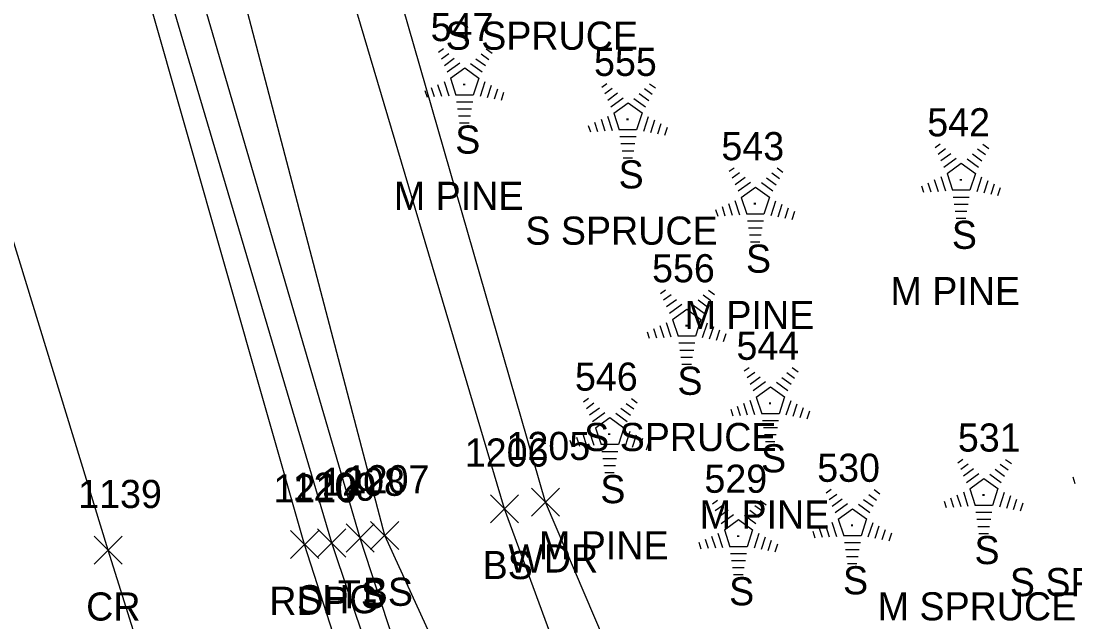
# Model space of a CAD drawing. Extents: x 1545627 to 1546562, y 571176 to 576667.
# Drawn here: x 1546172.5 to 1546247.4, y 571891 to 571933.8 of the extents above; entities that cross this region are included whole.
import ezdxf

# ---------------------------------------------------------------- set-up
doc = ezdxf.new("R2010")
doc.units = 0
for name, color, linetype in [('L_A', 7, 'Continuous'), ('L_C', 7, 'Continuous'), ('L_I', 7, 'Continuous'), ('L_TIC', 7, 'Continuous'), ('LAWA', 7, 'Continuous'), ('LELB', 7, 'Continuous'), ('LTC', 7, 'Continuous'), ('P_A', 7, 'Continuous'), ('P_I', 7, 'Continuous'), ('P_TIC', 7, 'Continuous'), ('PET', 7, 'Continuous'), ('PRC', 7, 'Continuous'), ('PSU', 7, 'Continuous')]:
    doc.layers.add(name, color=color, linetype=linetype)

msp = doc.modelspace()

# ---------------------------------------------------------------- linework, layer by layer
at = {"layer": 'L_TIC'}
for points in [[(1546208.815, 571898.546), (1546210.815, 571900.546)], [(1546210.815, 571898.546), (1546208.815, 571900.546)], [(1546205.909, 571898.078), (1546207.909, 571900.078)], [(1546207.909, 571898.078), (1546205.909, 571900.078)], [(1546197.39, 571896.178), (1546199.39, 571898.178)], [(1546199.39, 571896.178), (1546197.39, 571898.178)], [(1546195.649, 571895.999), (1546197.649, 571897.999)], [(1546197.649, 571895.999), (1546195.649, 571897.999)]]:
    msp.add_lwpolyline(points, dxfattribs=at)
at = {"layer": 'LAWA'}
msp.add_lwpolyline([(1546228.586, 571855.541), (1546209.815, 571899.546), (1546194.552, 571952.56), (1546185.852, 571982.338), (1546183.98, 571991.384), (1546179.112, 572029.569), (1546170.944, 572048.245), (1546164.758, 572064.391), (1546155.771, 572091.279), (1546144.336, 572123.946)], dxfattribs=at)
at = {"layer": 'LELB'}
for points in [[(1546347.404, 571535.241), (1546326.62, 571574.77), (1546309.351, 571609.13), (1546297.635, 571636.432), (1546292.788, 571646.222), (1546275.729, 571689.363), (1546263.627, 571715.111), (1546250.323, 571751.347), (1546233.4, 571797.155), (1546220.817, 571841.735), (1546218.613, 571853), (1546198.39, 571897.178), (1546185.101, 571947.883), (1546175.652, 571989.222), (1546174.94, 572003.263), (1546174.777, 572026.811), (1546167.554, 572047.439), (1546164.758, 572064.391), (1546160.424, 572092.892), (1546150.118, 572129.232)], [(1546346.375, 571534.64), (1546325.48, 571574.254), (1546308.892, 571608.63), (1546296.212, 571635.99), (1546273.967, 571687.639), (1546262.69, 571714.717), (1546248.75, 571750.385), (1546231.961, 571796.63), (1546217.305, 571838.705), (1546210.358, 571854.991), (1546196.649, 571896.999), (1546182.096, 571946.809), (1546169.64, 571995.561), (1546168.24, 572028.129), (1546158.043, 572044.974), (1546148.167, 572086.529), (1546140.639, 572120.601)], [(1546290.318, 571657.048), (1546276.567, 571693.199), (1546283.409, 571696.029), (1546285.218, 571707.812), (1546280.59, 571717.609), (1546272.325, 571717.419), (1546265.003, 571715.531), (1546255.381, 571753.558), (1546251.916, 571771.022), (1546251.669, 571784.619), (1546239.773, 571800.023), (1546225.642, 571844.556), (1546223.567, 571853.749), (1546206.909, 571899.078), (1546191.554, 571950.783), (1546183.98, 571991.384)]]:
    msp.add_lwpolyline(points, dxfattribs=at)
at = {"layer": 'LTC'}
for p, q in [((1546202.21, 571931.536), (1546202.565, 571931.793)), ((1546205.608, 571931.776), (1546206.028, 571931.471)), ((1546202.42, 571931.07), (1546202.949, 571931.454)), ((1546202.629, 571930.604), (1546203.333, 571931.116)), ((1546204.866, 571931.079), (1546205.545, 571930.586)), ((1546205.237, 571931.428), (1546205.787, 571931.028)), ((1546202.839, 571930.138), (1546203.717, 571930.776)), ((1546203.063, 571929.683), (1546204.075, 571930.418)), ((1546204.075, 571930.418), (1546205.072, 571929.693)), ((1546204.495, 571930.731), (1546205.305, 571930.142)), ((1546203.063, 571929.683), (1546203.45, 571928.49)), ((1546205.072, 571929.693), (1546204.681, 571928.49)), ((1546201.243, 571928.815), (1546201.395, 571928.347)), ((1546201.698, 571929.031), (1546201.91, 571928.38)), ((1546202.153, 571929.248), (1546202.425, 571928.413)), ((1546202.609, 571929.464), (1546202.94, 571928.445)), ((1546205.51, 571929.422), (1546205.172, 571928.383)), ((1546205.954, 571929.172), (1546205.667, 571928.287)), ((1546206.399, 571928.922), (1546206.162, 571928.192)), ((1546213.823, 571929.061), (1546214.177, 571929.318)), ((1546214.032, 571928.595), (1546214.561, 571928.979)), ((1546216.85, 571928.953), (1546217.399, 571928.554)), ((1546217.221, 571929.301), (1546217.64, 571928.997)), ((1546204.681, 571928.49), (1546203.45, 571928.49)), ((1546204.643, 571927.99), (1546203.498, 571927.99)), ((1546206.843, 571928.671), (1546206.656, 571928.097)), ((1546214.242, 571928.129), (1546214.946, 571928.641)), ((1546214.451, 571927.664), (1546215.33, 571928.302)), ((1546216.108, 571928.256), (1546216.917, 571927.667)), ((1546216.479, 571928.604), (1546217.158, 571928.111)), ((1546204.559, 571927.49), (1546203.57, 571927.49)), ((1546214.676, 571927.209), (1546215.688, 571927.943)), ((1546215.688, 571927.943), (1546216.685, 571927.218)), ((1546204.475, 571926.99), (1546203.643, 571926.99)), ((1546204.391, 571926.49), (1546203.716, 571926.49)), ((1546213.311, 571926.557), (1546213.522, 571925.905)), ((1546213.766, 571926.773), (1546214.037, 571925.938)), ((1546214.221, 571926.989), (1546214.552, 571925.97)), ((1546214.676, 571927.209), (1546215.063, 571926.015)), ((1546216.685, 571927.218), (1546216.294, 571926.015)), ((1546217.122, 571926.947), (1546216.784, 571925.908)), ((1546217.567, 571926.697), (1546217.279, 571925.812)), ((1546212.855, 571926.34), (1546213.007, 571925.872)), ((1546216.294, 571926.015), (1546215.063, 571926.015)), ((1546218.011, 571926.447), (1546217.774, 571925.717)), ((1546218.456, 571926.197), (1546218.269, 571925.622)), ((1546216.255, 571925.515), (1546215.111, 571925.515)), ((1546216.171, 571925.015), (1546215.183, 571925.015)), ((1546237.508, 571924.766), (1546237.863, 571925.024)), ((1546240.906, 571925.007), (1546241.325, 571924.702)), ((1546216.088, 571924.515), (1546215.256, 571924.515)), ((1546237.718, 571924.301), (1546238.247, 571924.685)), ((1546237.927, 571923.835), (1546238.631, 571924.346)), ((1546240.164, 571924.31), (1546240.843, 571923.816)), ((1546240.535, 571924.658), (1546241.085, 571924.259)), ((1546216.004, 571924.015), (1546215.329, 571924.015)), ((1546238.137, 571923.369), (1546239.015, 571924.007)), ((1546238.361, 571922.914), (1546239.373, 571923.649)), ((1546239.373, 571923.649), (1546240.37, 571922.924)), ((1546239.793, 571923.962), (1546240.603, 571923.373)), ((1546222.876, 571923.07), (1546223.231, 571923.327)), ((1546223.086, 571922.605), (1546223.615, 571922.989)), ((1546225.903, 571922.962), (1546226.453, 571922.563)), ((1546226.275, 571923.31), (1546226.694, 571923.006)), ((1546238.361, 571922.914), (1546238.748, 571921.721)), ((1546240.37, 571922.924), (1546239.979, 571921.721)), ((1546223.295, 571922.139), (1546223.999, 571922.65)), ((1546223.505, 571921.673), (1546224.383, 571922.311)), ((1546225.161, 571922.265), (1546225.971, 571921.677)), ((1546225.532, 571922.614), (1546226.212, 571922.12)), ((1546236.54, 571922.045), (1546236.693, 571921.577)), ((1546236.996, 571922.262), (1546237.208, 571921.61)), ((1546237.451, 571922.479), (1546237.723, 571921.643)), ((1546237.907, 571922.695), (1546238.238, 571921.676)), ((1546240.808, 571922.653), (1546240.47, 571921.613)), ((1546241.252, 571922.402), (1546240.965, 571921.518)), ((1546241.697, 571922.152), (1546241.46, 571921.423)), ((1546223.73, 571921.218), (1546224.741, 571921.952)), ((1546224.741, 571921.952), (1546225.738, 571921.227)), ((1546239.979, 571921.721), (1546238.748, 571921.721)), ((1546242.141, 571921.902), (1546241.954, 571921.328)), ((1546222.364, 571920.566), (1546222.576, 571919.914)), ((1546222.82, 571920.782), (1546223.091, 571919.947)), ((1546223.275, 571920.999), (1546223.606, 571919.98)), ((1546223.73, 571921.218), (1546224.117, 571920.025)), ((1546225.738, 571921.227), (1546225.347, 571920.025)), ((1546226.176, 571920.957), (1546225.838, 571919.917)), ((1546226.62, 571920.706), (1546226.333, 571919.822)), ((1546239.94, 571921.221), (1546238.796, 571921.221)), ((1546239.857, 571920.721), (1546238.868, 571920.721)), ((1546221.909, 571920.349), (1546222.061, 571919.881)), ((1546225.347, 571920.025), (1546224.117, 571920.025)), ((1546227.065, 571920.456), (1546226.828, 571919.727)), ((1546227.509, 571920.206), (1546227.322, 571919.632)), ((1546239.773, 571920.221), (1546238.941, 571920.221)), ((1546225.309, 571919.525), (1546224.164, 571919.525)), ((1546225.225, 571919.025), (1546224.237, 571919.025)), ((1546239.689, 571919.721), (1546239.014, 571919.721)), ((1546225.141, 571918.525), (1546224.31, 571918.525)), ((1546225.057, 571918.025), (1546224.382, 571918.025)), ((1546218.003, 571914.388), (1546218.357, 571914.646)), ((1546221.401, 571914.629), (1546221.82, 571914.324)), ((1546218.212, 571913.923), (1546218.741, 571914.307)), ((1546218.422, 571913.457), (1546219.125, 571913.968)), ((1546220.659, 571913.932), (1546221.338, 571913.438)), ((1546221.03, 571914.28), (1546221.579, 571913.881)), ((1546218.631, 571912.991), (1546219.51, 571913.629)), ((1546218.856, 571912.536), (1546219.868, 571913.271)), ((1546219.868, 571913.271), (1546220.865, 571912.546)), ((1546220.288, 571913.584), (1546221.097, 571912.995)), ((1546218.401, 571912.317), (1546218.732, 571911.298)), ((1546218.856, 571912.536), (1546219.243, 571911.343)), ((1546220.865, 571912.546), (1546220.473, 571911.343)), ((1546221.302, 571912.275), (1546220.964, 571911.235)), ((1546217.035, 571911.668), (1546217.187, 571911.2)), ((1546217.49, 571911.884), (1546217.702, 571911.233)), ((1546217.946, 571912.101), (1546218.217, 571911.265)), ((1546221.747, 571912.025), (1546221.459, 571911.14)), ((1546222.191, 571911.775), (1546221.954, 571911.045)), ((1546222.635, 571911.524), (1546222.449, 571910.95)), ((1546220.473, 571911.343), (1546219.243, 571911.343)), ((1546220.435, 571910.843), (1546219.29, 571910.843)), ((1546220.351, 571910.343), (1546219.363, 571910.343)), ((1546220.268, 571909.843), (1546219.436, 571909.843)), ((1546220.184, 571909.343), (1546219.509, 571909.343)), ((1546223.949, 571908.876), (1546224.303, 571909.134)), ((1546224.158, 571908.411), (1546224.687, 571908.795)), ((1546226.976, 571908.768), (1546227.525, 571908.369)), ((1546227.347, 571909.117), (1546227.766, 571908.812)), ((1546224.368, 571907.945), (1546225.072, 571908.456)), ((1546224.577, 571907.479), (1546225.456, 571908.117)), ((1546224.802, 571907.024), (1546225.814, 571907.759)), ((1546225.814, 571907.759), (1546226.811, 571907.034)), ((1546226.234, 571908.072), (1546227.043, 571907.483)), ((1546226.605, 571908.42), (1546227.284, 571907.926)), ((1546224.802, 571907.024), (1546225.189, 571905.831)), ((1546226.811, 571907.034), (1546226.42, 571905.831)), ((1546212.524, 571906.683), (1546212.878, 571906.94)), ((1546212.733, 571906.218), (1546213.262, 571906.602)), ((1546212.943, 571905.752), (1546213.647, 571906.263)), ((1546215.551, 571906.575), (1546216.1, 571906.176)), ((1546215.922, 571906.923), (1546216.341, 571906.619)), ((1546223.437, 571906.372), (1546223.648, 571905.72)), ((1546223.892, 571906.589), (1546224.163, 571905.753)), ((1546224.347, 571906.805), (1546224.678, 571905.786)), ((1546227.248, 571906.763), (1546226.91, 571905.723)), ((1546227.693, 571906.513), (1546227.405, 571905.628)), ((1546228.137, 571906.263), (1546227.9, 571905.533)), ((1546213.152, 571905.286), (1546214.031, 571905.924)), ((1546213.377, 571904.831), (1546214.389, 571905.565)), ((1546214.389, 571905.565), (1546215.386, 571904.84)), ((1546214.809, 571905.878), (1546215.618, 571905.29)), ((1546215.18, 571906.227), (1546215.859, 571905.733)), ((1546222.981, 571906.155), (1546223.133, 571905.688)), ((1546226.42, 571905.831), (1546225.189, 571905.831)), ((1546228.582, 571906.012), (1546228.395, 571905.438)), ((1546213.377, 571904.831), (1546213.764, 571903.638)), ((1546215.386, 571904.84), (1546214.995, 571903.638)), ((1546226.381, 571905.331), (1546225.237, 571905.331)), ((1546226.297, 571904.831), (1546225.309, 571904.831)), ((1546212.012, 571904.179), (1546212.223, 571903.527)), ((1546212.467, 571904.395), (1546212.738, 571903.56)), ((1546212.922, 571904.612), (1546213.253, 571903.593)), ((1546215.823, 571904.57), (1546215.485, 571903.53)), ((1546216.268, 571904.319), (1546215.98, 571903.435)), ((1546216.712, 571904.069), (1546216.475, 571903.34)), ((1546226.214, 571904.331), (1546225.382, 571904.331)), ((1546211.556, 571903.962), (1546211.708, 571903.494)), ((1546214.995, 571903.638), (1546213.764, 571903.638)), ((1546217.157, 571903.819), (1546216.97, 571903.245)), ((1546226.13, 571903.831), (1546225.455, 571903.831)), ((1546214.956, 571903.138), (1546213.812, 571903.138)), ((1546214.872, 571902.638), (1546213.884, 571902.638)), ((1546239.118, 571902.352), (1546239.473, 571902.609)), ((1546242.516, 571902.592), (1546242.935, 571902.287)), ((1546214.789, 571902.138), (1546213.957, 571902.138)), ((1546239.328, 571901.886), (1546239.857, 571902.27)), ((1546239.537, 571901.42), (1546240.241, 571901.932)), ((1546241.774, 571901.895), (1546242.453, 571901.402)), ((1546242.145, 571902.244), (1546242.695, 571901.844)), ((1546214.705, 571901.638), (1546214.03, 571901.638)), ((1546239.747, 571900.954), (1546240.625, 571901.592)), ((1546239.971, 571900.499), (1546240.983, 571901.234)), ((1546240.983, 571901.234), (1546241.98, 571900.509)), ((1546241.403, 571901.547), (1546242.213, 571900.958)), ((1546247.295, 571901.352), (1546247.447, 571900.884)), ((1546229.776, 571900.203), (1546230.13, 571900.461)), ((1546233.174, 571900.444), (1546233.593, 571900.139)), ((1546239.517, 571900.28), (1546239.848, 571899.261)), ((1546239.971, 571900.499), (1546240.358, 571899.306)), ((1546241.98, 571900.509), (1546241.589, 571899.306)), ((1546221.679, 571899.424), (1546222.033, 571899.682)), ((1546225.077, 571899.665), (1546225.496, 571899.36)), ((1546229.985, 571899.738), (1546230.514, 571900.122)), ((1546230.195, 571899.272), (1546230.899, 571899.783)), ((1546232.432, 571899.747), (1546233.111, 571899.253)), ((1546232.803, 571900.095), (1546233.352, 571899.696)), ((1546238.15, 571899.631), (1546238.303, 571899.163)), ((1546238.606, 571899.847), (1546238.818, 571899.196)), ((1546239.061, 571900.064), (1546239.333, 571899.229)), ((1546242.418, 571900.238), (1546242.08, 571899.199)), ((1546242.862, 571899.988), (1546242.575, 571899.103)), ((1546243.307, 571899.738), (1546243.07, 571899.008)), ((1546221.888, 571898.959), (1546222.417, 571899.343)), ((1546222.098, 571898.493), (1546222.801, 571899.004)), ((1546224.335, 571898.968), (1546225.014, 571898.474)), ((1546224.706, 571899.317), (1546225.255, 571898.917)), ((1546230.404, 571898.806), (1546231.283, 571899.444)), ((1546230.629, 571898.351), (1546231.641, 571899.086)), ((1546231.641, 571899.086), (1546232.638, 571898.361)), ((1546232.061, 571899.399), (1546232.87, 571898.81)), ((1546241.589, 571899.306), (1546240.358, 571899.306)), ((1546241.55, 571898.806), (1546240.406, 571898.806)), ((1546243.751, 571899.487), (1546243.564, 571898.913)), ((1546222.307, 571898.027), (1546223.186, 571898.665)), ((1546222.532, 571897.572), (1546223.544, 571898.307)), ((1546223.544, 571898.307), (1546224.541, 571897.582)), ((1546223.964, 571898.62), (1546224.773, 571898.031)), ((1546230.174, 571898.132), (1546230.505, 571897.113)), ((1546230.629, 571898.351), (1546231.016, 571897.158)), ((1546232.638, 571898.361), (1546232.247, 571897.158)), ((1546233.075, 571898.09), (1546232.737, 571897.05)), ((1546241.467, 571898.306), (1546240.478, 571898.306)), ((1546222.077, 571897.353), (1546222.408, 571896.334)), ((1546222.532, 571897.572), (1546222.919, 571896.379)), ((1546224.541, 571897.582), (1546224.149, 571896.379)), ((1546224.978, 571897.311), (1546224.64, 571896.272)), ((1546228.808, 571897.483), (1546228.96, 571897.015)), ((1546229.264, 571897.699), (1546229.475, 571897.048)), ((1546229.719, 571897.916), (1546229.99, 571897.08)), ((1546233.52, 571897.84), (1546233.232, 571896.955)), ((1546233.964, 571897.59), (1546233.727, 571896.86)), ((1546234.409, 571897.339), (1546234.222, 571896.765)), ((1546241.383, 571897.806), (1546240.551, 571897.806)), ((1546241.299, 571897.306), (1546240.624, 571897.306)), ((1546220.711, 571896.704), (1546220.863, 571896.236)), ((1546221.166, 571896.92), (1546221.378, 571896.269)), ((1546221.622, 571897.137), (1546221.893, 571896.302)), ((1546225.423, 571897.061), (1546225.135, 571896.176)), ((1546225.867, 571896.811), (1546225.63, 571896.081)), ((1546226.311, 571896.56), (1546226.125, 571895.986)), ((1546232.247, 571897.158), (1546231.016, 571897.158)), ((1546232.208, 571896.658), (1546231.064, 571896.658)), ((1546224.149, 571896.379), (1546222.919, 571896.379)), ((1546224.111, 571895.879), (1546222.966, 571895.879)), ((1546232.124, 571896.158), (1546231.136, 571896.158)), ((1546224.027, 571895.379), (1546223.039, 571895.379)), ((1546232.041, 571895.658), (1546231.209, 571895.658)), ((1546231.957, 571895.158), (1546231.282, 571895.158)), ((1546223.944, 571894.879), (1546223.112, 571894.879)), ((1546223.86, 571894.379), (1546223.185, 571894.379))]:
    msp.add_line(p, q, dxfattribs=at)
at = {"layer": 'P_TIC'}
for points in [[(1546191.697, 571895.534), (1546193.697, 571897.534)], [(1546193.697, 571895.534), (1546191.697, 571897.534)], [(1546193.623, 571895.648), (1546195.623, 571897.648)], [(1546195.623, 571895.648), (1546193.623, 571897.648)], [(1546177.735, 571895.131), (1546179.735, 571897.131)], [(1546179.735, 571895.131), (1546177.735, 571897.131)]]:
    msp.add_lwpolyline(points, dxfattribs=at)
at = {"layer": 'PET'}
msp.add_lwpolyline([(1546559.083, 571194.504), (1546529.754, 571240.451), (1546499.791, 571284.884), (1546470.8, 571327.721), (1546443.13, 571367.677), (1546417.679, 571406.902), (1546392.946, 571446.313), (1546370.2, 571483.985), (1546352.755, 571514.997), (1546343.407, 571532.432), (1546322.939, 571573.038), (1546306.849, 571607.127), (1546293.983, 571634.557), (1546271.4, 571685.961), (1546259.459, 571713.473), (1546245.431, 571748.527), (1546227.668, 571795.217), (1546213.044, 571834.88), (1546205.182, 571857.755), (1546192.697, 571896.534), (1546178.724, 571945.469), (1546165.665, 571996.104)], dxfattribs=at)
at = {"layer": 'PRC'}
msp.add_lwpolyline([(1546547.342, 571187.72), (1546518.743, 571231.857), (1546487.308, 571278.432), (1546459.326, 571318.892), (1546430.574, 571360.766), (1546405.961, 571398.261), (1546380.249, 571440.095), (1546358.534, 571476.988), (1546340.409, 571508.44), (1546330.222, 571526.947), (1546310.108, 571567.468), (1546291.289, 571606.946), (1546272.42, 571649.009), (1546255.626, 571687.658), (1546242.527, 571719.45), (1546229.288, 571753.104), (1546216.077, 571786.744), (1546203.345, 571821.005), (1546191.258, 571856.193), (1546178.735, 571896.131), (1546167.498, 571932.695), (1546157.434, 571971.538), (1546147.892, 572011.795)], dxfattribs=at)
at = {"layer": 'PSU'}
msp.add_lwpolyline([(1546344.909, 571533.751), (1546324.237, 571573.752), (1546307.569, 571607.607), (1546295.255, 571635.337), (1546272.392, 571686.555), (1546261.3, 571714.23), (1546246.813, 571749.297), (1546229.824, 571796.031), (1546214.931, 571836.379), (1546208.219, 571856.105), (1546194.623, 571896.648), (1546180.076, 571945.808), (1546167.396, 571995.967), (1546161.656, 572024.838), (1546155.575, 572044.541)], dxfattribs=at)

# ---------------------------------------------------------------- texts
at = {"layer": 'L_A'}
for s, p in [('S', (1546203.401, 571924.327)), ('S', (1546215.013, 571921.853)), ('S', (1546238.699, 571917.558)), ('S', (1546224.067, 571915.862)), ('S', (1546219.193, 571907.18)), ('S', (1546225.139, 571901.668)), ('S', (1546213.714, 571899.475)), ('WDR', (1546207.178, 571894.546)), ('S', (1546240.309, 571895.143)), ('BS', (1546205.35, 571894.078)), ('S', (1546230.966, 571892.995)), ('TS', (1546195.059, 571891.999)), ('BS', (1546196.831, 571892.178)), ('S', (1546222.869, 571892.216))]:
    msp.add_text(s, height=2, dxfattribs=at).set_placement(p)
at = {"layer": 'L_C'}
for s, p in [('S SPRUCE', (1546202.721, 571931.715)), ('M PINE', (1546199.038, 571920.327)), ('S SPRUCE', (1546208.383, 571917.853)), ('M PINE', (1546234.336, 571913.558)), ('M PINE', (1546219.705, 571911.862)), ('S SPRUCE', (1546212.563, 571903.18)), ('M PINE', (1546220.777, 571897.668)), ('M PINE', (1546209.352, 571895.475)), ('S SPRUCE', (1546242.823, 571892.865)), ('M SPRUCE', (1546233.427, 571891.143))]:
    msp.add_text(s, height=2, dxfattribs=at).set_placement(p)
at = {"layer": 'L_I'}
for s, p in [('547', (1546201.653, 571932.327)), ('555', (1546213.265, 571929.853)), ('542', (1546236.951, 571925.558)), ('543', (1546222.319, 571923.862)), ('556', (1546217.39, 571915.18)), ('544', (1546223.391, 571909.668)), ('546', (1546211.911, 571907.475)), ('531', (1546239.128, 571903.143)), ('1206', (1546204.082, 571902.078)), ('1205', (1546207.044, 571902.546)), ('530', (1546229.132, 571900.995)), ('1208', (1546193.878, 571899.999)), ('1207', (1546195.618, 571900.178)), ('529', (1546221.113, 571900.216))]:
    msp.add_text(s, height=2, dxfattribs=at).set_placement(p)
at = {"layer": 'LTC'}
for p in [(1546203.958, 571929.431), (1546215.57, 571926.957), (1546239.255, 571922.662), (1546224.624, 571920.966), (1546219.75, 571912.284), (1546225.696, 571906.772), (1546214.271, 571904.579), (1546240.865, 571900.247), (1546231.523, 571898.099), (1546223.426, 571897.32)]:
    msp.add_text('.', height=1.037, rotation=270, dxfattribs=at).set_placement(p)
at = {"layer": 'P_A'}
for s, p in [('RDP', (1546190.186, 571891.534)), ('SHG', (1546192.158, 571891.648)), ('CR', (1546177.169, 571891.131))]:
    msp.add_text(s, height=2, dxfattribs=at).set_placement(p)
at = {"layer": 'P_I'}
for s, p in [('1139', (1546176.602, 571899.131)), ('1210', (1546190.485, 571899.534)), ('1209', (1546191.843, 571899.648))]:
    msp.add_text(s, height=2, dxfattribs=at).set_placement(p)

doc.saveas('drawing.dxf')
